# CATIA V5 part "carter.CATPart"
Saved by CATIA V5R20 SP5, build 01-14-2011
Part number: carter
Bounding box of the stored display mesh (mm): x 0 to 1400, y -650 to 0, z -110 to 110
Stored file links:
  M:\EU_thinkMotion\IAO_2010\iao\IAO_MMS_Groupe2\IAO_MMS_Groupe2\mayache\mayache\Pièces\carter.CATPart
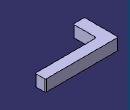
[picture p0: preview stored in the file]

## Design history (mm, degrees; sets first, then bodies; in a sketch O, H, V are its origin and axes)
Parameters
  longcarter = 1400 mm
  largcarter = 650 mm
  ptlargcarter = 200 mm
  ptlong = 220 mm
  epcarter = 220 mm
  raytube = 60 mm
  proftrou = 100 mm
  rayboule = 30 mm
Body1 (main body)
  Sketch1 on xy-plane, origin (0, 0, 0), H (1, 0, 0), V (0, 1, 0)
    line L1 (0, 0) -> (0, -650)
    line L2 (0, -650) -> (220, -650)
    line L3 (220, -650) -> (220, -200)
    line L4 (220, -200) -> (1400, -200)
    line L5 (1400, -200) -> (1400, 0)
    point P5 (1400, 0)
    line L6 (1400, 0) -> (0, 0)
    length L1 = 650 {= largcarter}
    length L6 = 1400 {= longcarter}
    length L5 = 200 {= ptlargcarter}
    length L2 = 220 {= ptlong}
    vertical: L1 V, L3 V, L5 V
    horizontal: L2 H, L4 H, L6 H
    coincidence: P5 H
  Pad1: profile Sketch1, direction (0, 0, -1), length 110 {= epcarter/2}, mirrored extent
  Fillet1: radius 30, on edge [face of Pad1 from Sketch1.L3 | face of Pad1 from Sketch1.L4]
  Fillet2: radius 20, on edge [face of Pad1 from Sketch1.L2 | face of Pad1 from Sketch1.L3]; edge [face of Pad1 from Sketch1.L1 | face of Pad1 from Sketch1.L2]; edge [face of Pad1 from Sketch1.L4 | face of Pad1 from Sketch1.L5]; edge [face of Pad1 from Sketch1.L5 | face of Pad1 from Sketch1.L6]; edge [face of Pad1 from Sketch1.L6 | face of Pad1 from Sketch1.L1]
  Body2
    Sketch2 on face of Pad1 from Sketch1.L2, origin (0, -650, 0), H (1, 0, 0), V (0, 0, 1)
      circle A1 centre (110, 0) radius 60
      point P1 (110, 0)
      reference projected line E1 (0, -110) -> (240, -110) from edge [end face of Pad1 | face of Pad1 from Sketch1.L2]
      reference projected line E2 (0, 0) -> (0, -220) from edge [face of Pad1 from Sketch1.L1 | face of Fillet2]
      distance P1 E1 = 110 {= epcarter /2}
      distance P1 E2 = 110 {= ptlong /2}
      radius A1 = 60 {= raytube}
    Pad2: profile Sketch2, direction (0, 1, 0), length 100 {= proftrou}
  Remove1: tool Body2
  Body3
    Sketch3 on xy-plane, origin (0, 0, 0), H (1, 0, 0), V (0, 1, 0)
      line L1 (1220, -155.5556) -> (1220, -215.5556)
      point P1 (1220, -155.5556)
      reference projected line E1 (1200, 0) -> (0, 0) from edge [face of Pad1 from Sketch1.L6 | start face of Pad1]
      reference projected line E2 (220, -650) -> (220, -200) from edge [face of Pad1 from Sketch1.L3 | start face of Pad1]
      arc A1 centre (1220, -185.5556) radius 30 from (1220, -155.5556) to (1220, -215.5556) ccw
      length L1 = 60 {= rayboule*2}
      distance P1 E1 = 155.5556 {= ptlargcarter -(ptlargcarter /4.5)}
      distance E2 L1 = 1000 {= longcarter /1.4}
      radius A1 = 30 {= rayboule}
      vertical: L1 V
    Shaft1: profile Sketch3, axis Sketch3.L1, angle 360
  Remove2: tool Body3
  Point1: type Center, Curve face of Shaft1 from Sketch3.A1
  Line1: type Normal, RefPoint Point1, RefSkin start face of Pad1, Start 0, End 20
